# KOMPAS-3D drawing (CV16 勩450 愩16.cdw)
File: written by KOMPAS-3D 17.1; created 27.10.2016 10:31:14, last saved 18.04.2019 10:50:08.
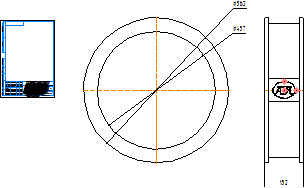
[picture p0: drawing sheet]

Sheet 1: A4, portrait

Title block, sheet 1: name: CV16 Ду450 Ру16; material: Внимание! Данный продукт является объектом авторского права ООО «Торговый Дом АДЛ». / Запрещается изменение, копирование, распространение / (в том числе путем копирования на другие сайты и ресурсы в Интернете) / или любое иное использование информации и объектов без предварительного / согласия правообладателя (ООО «Торговый Дом АДЛ»).; mass: 280,8; sheets: 1; organisation: ООО "Торговый дом АДЛ"; sheet format: A4; stored path: \\adlc.lan\data\АДЛ_ПКД\3D-модели\ADL production\Клапаны обратные ГРАНЛОК\CV16\KOMPAS 2D\CV16 Ду450 Ру16.cdw

Views: Вид 1, Проекционный вид 2
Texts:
  Klimkovich
  ADL
Dimensions and other numbers on the sheet: 562; 457; 152; 1:1; 1; 280,8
